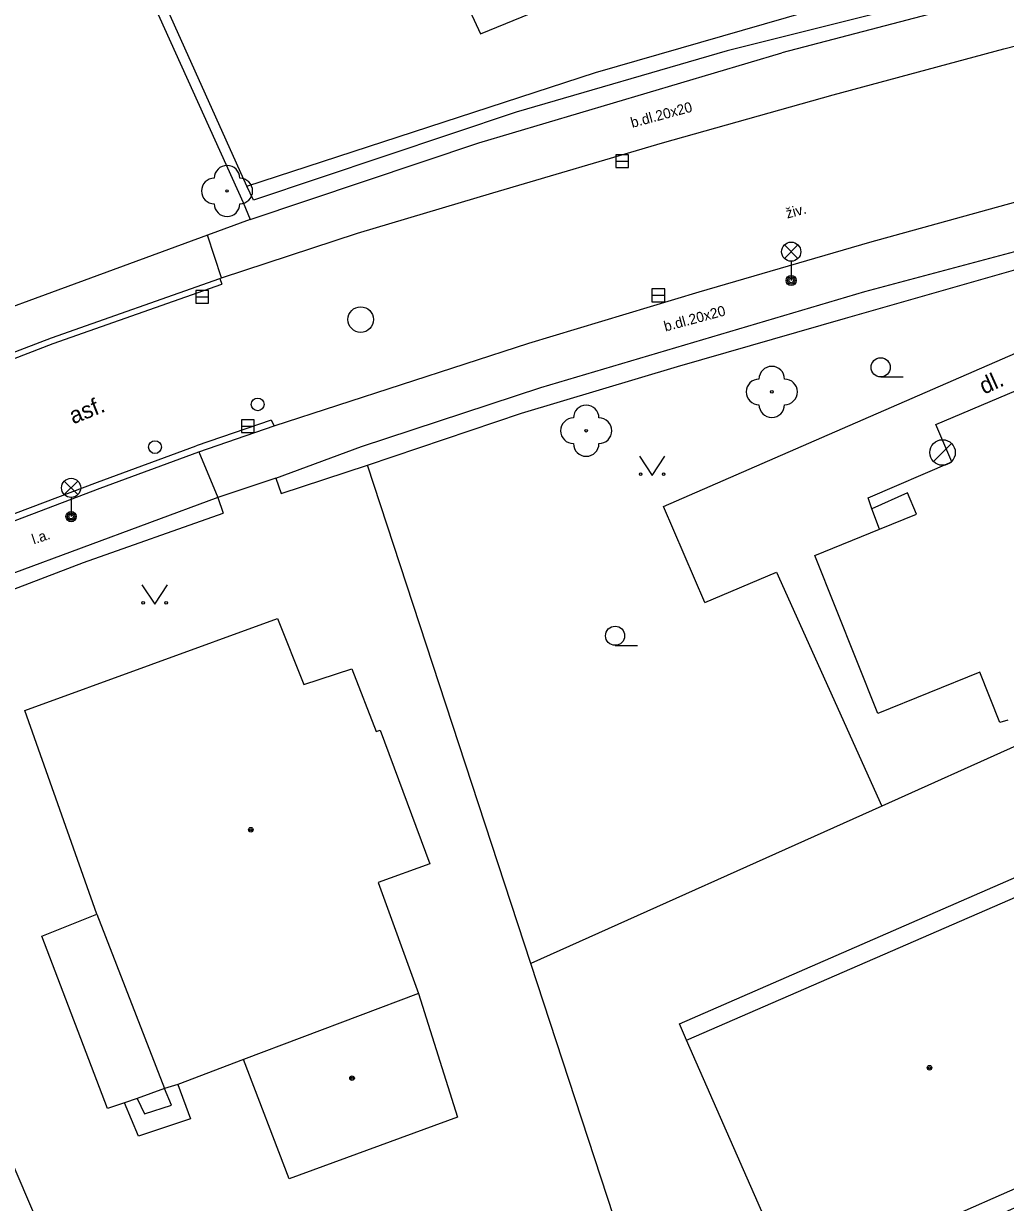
# Model space of a CAD drawing. Extents: x -600309 to -598967, y -1161267 to -1160292.
# Drawn here: x -599866.65 to -599828.24, y -1160382.2 to -1160336.08 of the extents above; entities that cross this region are included whole.
import ezdxf

# ---------------------------------------------------------------- set-up
doc = ezdxf.new("R2010")
doc.units = 0
for name, color, linetype in [('Level 10', 7, 'Continuous'), ('Level 11', 7, 'Continuous'), ('Level 21', 7, 'Continuous'), ('Level 22', 7, 'Continuous'), ('Level 27', 7, 'Continuous'), ('Level 28', 7, 'Continuous'), ('Level 33', 7, 'Continuous'), ('Level 36', 7, 'Continuous'), ('Level 39', 7, 'Continuous'), ('Level 40', 7, 'Continuous'), ('Level 5', 7, 'Continuous'), ('Level 51', 7, 'Continuous'), ('Level 7', 7, 'Continuous'), ('Level 8', 7, 'Continuous')]:
    doc.layers.add(name, color=color, linetype=linetype)

msp = doc.modelspace()

# ---------------------------------------------------------------- linework, layer by layer
at = {"layer": 'Level 10'}
for points in [[(-599828.3, -1160337.07), (-599821.59, -1160335.35)], [(-599841.65, -1160340.75), (-599834.98, -1160338.87), (-599828.3, -1160337.07)], [(-599848.29, -1160342.7), (-599841.65, -1160340.75)], [(-599872.76, -1160351.13), (-599865.56, -1160348.38), (-599858.97, -1160346.05), (-599858.91, -1160346.03), (-599853.59, -1160344.28), (-599848.29, -1160342.7)], [(-599833.54, -1160344.63), (-599826.84, -1160342.78)], [(-599840.22, -1160346.57), (-599833.54, -1160344.63)], [(-599846.88, -1160348.58), (-599840.22, -1160346.57)], [(-599870.49, -1160356.85), (-599863.65, -1160354.25), (-599859.79, -1160352.83), (-599856.85, -1160351.82), (-599846.88, -1160348.58)]]:
    msp.add_lwpolyline(points, dxfattribs=at)
at = {"layer": 'Level 11'}
for points in [[(-599858.91, -1160346.03), (-599859.46, -1160344.36)], [(-599872.69, -1160351.38), (-599865.49, -1160348.6), (-599858.9, -1160346.27)], [(-599858.97, -1160346.05), (-599858.9, -1160346.27)], [(-599840, -1160358.73), (-599841.62, -1160354.97), (-599835.42, -1160352.27), (-599822.39, -1160346.6), (-599819.48, -1160346.47)], [(-599856.96, -1160351.59), (-599859.9, -1160352.6)], [(-599856.96, -1160351.59), (-599856.85, -1160351.82)], [(-599870.57, -1160356.59), (-599863.76, -1160354.02), (-599859.9, -1160352.6)], [(-599859.79, -1160352.83), (-599859.05, -1160354.62)], [(-599833.17, -1160355.86), (-599833.4699, -1160355.06)], [(-599840, -1160358.73), (-599837.2, -1160357.54), (-599833.08, -1160366.7)], [(-599840.99, -1160375.21), (-599825.27, -1160368.35), (-599824.76, -1160369.51), (-599824.61, -1160369.85), (-599823.34, -1160372.73), (-599823.24, -1160372.95), (-599823.05, -1160373.39), (-599822.44, -1160374.78), (-599820.53, -1160379.13), (-599829.27, -1160383.04), (-599829.11, -1160383.4), (-599832.96, -1160385.07), (-599833.17, -1160384.73), (-599836.23, -1160385.98), (-599836.49, -1160385.46)], [(-599865.93, -1160371.78), (-599863.78, -1160370.92)], [(-599863.36, -1160378.53), (-599865.93, -1160371.78)], [(-599840.7199, -1160375.85), (-599840.99, -1160375.21)], [(-599861.13, -1160377.74), (-599862.21, -1160378.13)], [(-599862.21, -1160378.13), (-599861.92, -1160378.74), (-599860.86, -1160378.4), (-599861.13, -1160377.74)], [(-599860.62, -1160377.59), (-599860.12, -1160378.93)], [(-599862.21, -1160378.13), (-599862.7, -1160378.3)], [(-599862.7, -1160378.3), (-599863.36, -1160378.53)], [(-599862.1599, -1160379.61), (-599862.7, -1160378.3)], [(-599860.12, -1160378.93), (-599862.1599, -1160379.61)]]:
    msp.add_lwpolyline(points, dxfattribs=at)
at = {"layer": 'Level 21'}
msp.add_lwpolyline([(-599857.91, -1160342.44), (-599844.28, -1160338), (-599835.18, -1160335.37)], dxfattribs=at)
at = {"layer": 'Level 22'}
for centre in [(-599858.69, -1160342.63), (-599837.38, -1160350.49), (-599844.64, -1160352.01)]:
    msp.add_circle(centre, 0.05, dxfattribs=at)
for centre, start, end in [((-599858.69, -1160342.13), 0, 180), ((-599859.19, -1160342.63), 90, 270), ((-599858.19, -1160342.63), 270, 90), ((-599858.69, -1160343.13), 180, 0), ((-599837.38, -1160349.99), 0, 180), ((-599837.88, -1160350.49), 90, 270), ((-599836.88, -1160350.49), 270, 90), ((-599844.64, -1160351.51), 0, 180), ((-599837.38, -1160350.99), 180, 0), ((-599845.14, -1160352.01), 90, 270), ((-599844.14, -1160352.01), 270, 90), ((-599844.64, -1160352.51), 180, 0)]:
    msp.add_arc(centre, 0.5, start, end, dxfattribs=at)
at = {"layer": 'Level 27'}
for p, q in [((-599843.48, -1160341.46), (-599842.98, -1160341.46)), ((-599859.91, -1160346.77), (-599859.41, -1160346.77)), ((-599842.07, -1160346.71), (-599841.57, -1160346.71)), ((-599858.13, -1160351.83), (-599857.63, -1160351.83)), ((-599831.054, -1160353.213), (-599830.347, -1160352.506))]:
    msp.add_line(p, q, dxfattribs=at)
for points in [[(-599843.48, -1160341.71), (-599842.98, -1160341.71), (-599842.98, -1160341.21), (-599843.48, -1160341.21)], [(-599859.91, -1160347.02), (-599859.41, -1160347.02), (-599859.41, -1160346.52), (-599859.91, -1160346.52)], [(-599842.07, -1160346.96), (-599841.57, -1160346.96), (-599841.57, -1160346.46), (-599842.07, -1160346.46)], [(-599858.13, -1160352.08), (-599857.63, -1160352.08), (-599857.63, -1160351.58), (-599858.13, -1160351.58)]]:
    msp.add_lwpolyline(points, close=True, dxfattribs=at)
for centre in [(-599853.46, -1160347.66), (-599830.7, -1160352.86)]:
    msp.add_circle(centre, 0.5, dxfattribs=at)
at = {"layer": 'Level 28'}
for centre in [(-599857.49, -1160350.98), (-599861.51, -1160352.65)]:
    msp.add_circle(centre, 0.25, dxfattribs=at)
at = {"layer": 'Level 33'}
for p, q in [((-599836.885, -1160345.27), (-599836.355, -1160344.74)), ((-599836.885, -1160344.74), (-599836.355, -1160345.27)), ((-599836.62, -1160345.38), (-599836.62, -1160346.13)), ((-599865.055, -1160354.51), (-599864.525, -1160353.98)), ((-599865.055, -1160353.98), (-599864.525, -1160354.51)), ((-599864.79, -1160354.62), (-599864.79, -1160355.37))]:
    msp.add_line(p, q, dxfattribs=at)
for centre, radius in [((-599836.62, -1160345.005), 0.375), ((-599836.62, -1160346.13), 0.2), ((-599836.62, -1160346.13), 0.1445), ((-599836.62, -1160346.13), 0.0876), ((-599864.79, -1160354.245), 0.375), ((-599864.79, -1160355.37), 0.2), ((-599864.79, -1160355.37), 0.1445), ((-599864.79, -1160355.37), 0.0876)]:
    msp.add_circle(centre, radius, dxfattribs=at)
at = {"layer": 'Level 36'}
for p, q in [((-599833.12, -1160349.905), (-599832.245, -1160349.905)), ((-599843.51, -1160360.405), (-599842.635, -1160360.405))]:
    msp.add_line(p, q, dxfattribs=at)
for points in [[(-599842.56, -1160353.01), (-599842.06, -1160353.76), (-599841.56, -1160353.01)], [(-599862.02, -1160358.04), (-599861.52, -1160358.79), (-599861.02, -1160358.04)]]:
    msp.add_lwpolyline(points, dxfattribs=at)
for centre, radius in [((-599833.1201, -1160349.5299), 0.375), ((-599842.5102, -1160353.7098), 0.05), ((-599841.6108, -1160353.7098), 0.05), ((-599861.9702, -1160358.7398), 0.05), ((-599861.0708, -1160358.7398), 0.05), ((-599843.5101, -1160360.0299), 0.375)]:
    msp.add_circle(centre, radius, dxfattribs=at)
at = {"layer": 'Level 39'}
for centre, radius in [((-599857.76, -1160367.62), 0.09), ((-599857.76, -1160367.62), 0.0398), ((-599831.21, -1160376.93), 0.09), ((-599831.21, -1160376.93), 0.0398), ((-599853.8, -1160377.34), 0.09), ((-599853.8, -1160377.34), 0.0398)]:
    msp.add_circle(centre, radius, dxfattribs=at)
at = {"layer": 'Level 5'}
for points in [[(-599851.05, -1160331.58), (-599848.77, -1160336.48)], [(-599848.77, -1160336.48), (-599844.52, -1160334.73)], [(-599830.96, -1160351.77), (-599825.7, -1160349.53)], [(-599830.33, -1160353.2199), (-599830.96, -1160351.77)], [(-599833.61, -1160354.64), (-599830.33, -1160353.2199)], [(-599833.4699, -1160355.06), (-599833.61, -1160354.64)], [(-599832.07, -1160354.44), (-599833.4699, -1160355.06)], [(-599831.7199, -1160355.27), (-599832.07, -1160354.44)], [(-599833.17, -1160355.86), (-599831.7199, -1160355.27)], [(-599835.69, -1160356.89), (-599833.17, -1160355.86)], [(-599833.23, -1160363.07), (-599835.69, -1160356.89)], [(-599866.6, -1160362.96), (-599856.7199, -1160359.35)], [(-599856.7199, -1160359.35), (-599855.68, -1160361.94)], [(-599855.68, -1160361.94), (-599853.81, -1160361.32)], [(-599853.81, -1160361.32), (-599852.86, -1160363.77)], [(-599829.24, -1160361.45), (-599833.23, -1160363.07)], [(-599828.46, -1160363.42), (-599829.24, -1160361.45)], [(-599863.78, -1160370.92), (-599866.6, -1160362.96)], [(-599828.14, -1160363.33), (-599828.46, -1160363.42)], [(-599852.86, -1160363.77), (-599852.7, -1160363.7199)], [(-599852.7, -1160363.7199), (-599850.76, -1160368.95)], [(-599850.76, -1160368.95), (-599852.78, -1160369.69)], [(-599840.7199, -1160375.85), (-599825.95, -1160369.43)], [(-599852.78, -1160369.69), (-599851.2, -1160374.02)], [(-599863.78, -1160370.92), (-599861.13, -1160377.74)], [(-599851.2, -1160374.02), (-599858.04, -1160376.61)], [(-599851.2, -1160374.02), (-599849.67, -1160378.87)], [(-599836.49, -1160385.46), (-599840.7199, -1160375.85)], [(-599858.04, -1160376.61), (-599860.62, -1160377.59)], [(-599856.26, -1160381.28), (-599858.04, -1160376.61)], [(-599860.62, -1160377.59), (-599861.13, -1160377.74)], [(-599849.67, -1160378.87), (-599856.26, -1160381.28)], [(-599821.74, -1160378.9699), (-599836.49, -1160385.46)]]:
    msp.add_lwpolyline(points, dxfattribs=at)
at = {"layer": 'Level 51'}
for points in [[(-599827.8, -1160364.33), (-599833.08, -1160366.7), (-599846.8, -1160372.85)], [(-599859.52, -1160398.37), (-599872.08, -1160369.01)], [(-599841.07, -1160390.37), (-599846.8, -1160372.85)]]:
    msp.add_lwpolyline(points, dxfattribs=at)
at = {"layer": 'Level 7'}
for points in [[(-599827.36, -1160315.16), (-599822.82, -1160325.73), (-599822.58, -1160326.28), (-599821.39, -1160329.05), (-599821.82, -1160329.93), (-599822.62, -1160331.51), (-599823.77, -1160333.75), (-599836.99, -1160337.22)], [(-599827.54, -1160315.92), (-599821.87, -1160329.04), (-599824.1, -1160333.44), (-599832.08, -1160335.39), (-599839.12, -1160337.15), (-599847.38, -1160339.54), (-599857.6599, -1160342.99), (-599857.91, -1160342.44), (-599865.7199, -1160325.07)], [(-599866.31, -1160324.79), (-599864.48, -1160328.85), (-599863.78, -1160330.41), (-599858.06, -1160343.08)], [(-599848.84, -1160340.74), (-599836.99, -1160337.22)], [(-599857.78, -1160343.75), (-599848.84, -1160340.74)], [(-599858.06, -1160343.08), (-599857.78, -1160343.75)], [(-599846.41, -1160350.32), (-599833.74, -1160346.56), (-599819.85, -1160342.86)], [(-599853.2, -1160353.35), (-599847.17, -1160351.32), (-599841.07, -1160349.49), (-599834.49, -1160347.6), (-599819.89, -1160343.43), (-599818.36, -1160344.2), (-599818, -1160344.38)], [(-599857.78, -1160343.75), (-599859.46, -1160344.36), (-599874.09, -1160349.73)], [(-599856.78, -1160353.86), (-599853.43, -1160352.62), (-599846.41, -1160350.32)], [(-599856.57, -1160354.47), (-599853.2, -1160353.35)], [(-599846.8, -1160372.85), (-599853.2, -1160353.35)], [(-599856.78, -1160353.86), (-599856.57, -1160354.47)], [(-599859.05, -1160354.62), (-599869.75, -1160358.58)], [(-599859.05, -1160354.62), (-599858.84, -1160355.24)], [(-599871.27, -1160359.83), (-599864.31, -1160357.1599), (-599858.84, -1160355.24)]]:
    msp.add_lwpolyline(points, dxfattribs=at)
at = {"layer": 'Level 8'}
msp.add_lwpolyline([(-599856.78, -1160353.86), (-599859.05, -1160354.62)], dxfattribs=at)

# ---------------------------------------------------------------- texts
at = {"layer": 'Level 40'}
for s, height, rotation, p in [('b.dl.20x20', 0.39997, 15.08342, (-599842.84, -1160340.16)), ('živ.', 0.4, 15.08342, (-599836.77, -1160343.71)), ('b.dl.20x20', 0.39997, 15.08342, (-599841.54, -1160348.13)), ('dl.', 0.65, 24.26383, (-599829.08, -1160350.6)), ('asf.', 0.65, 21.58, (-599864.71, -1160351.76)), ('l.a.', 0.4, 18.62001, (-599866.25, -1160356.46))]:
    msp.add_text(s, height=height, rotation=rotation, dxfattribs=at).set_placement(p)

doc.saveas('drawing.dxf')
